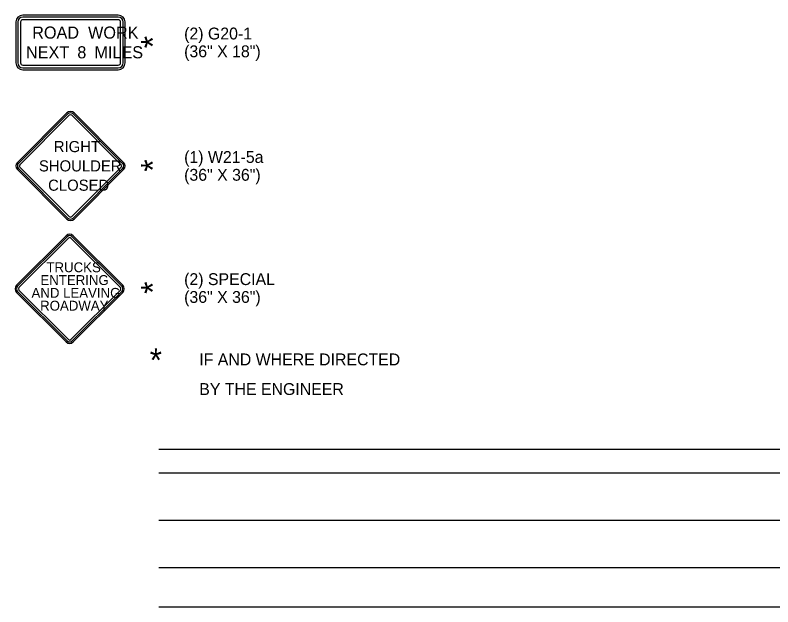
# Model space of a CAD drawing. Extents: x 913 to 1207, y 319 to 519.
# Drawn here: x 913.1 to 989.8, y 413.6 to 473.5 of the extents above; entities that cross this region are included whole.
import ezdxf

# ---------------------------------------------------------------- set-up
doc = ezdxf.new("R2010")
doc.units = 0
doc.layers.add('R_Annotation', color=7, linetype='Continuous')
doc.layers.add('R_Draft', color=7, linetype='Continuous')

msp = doc.modelspace()

# ---------------------------------------------------------------- linework, layer by layer
at = {"layer": 'R_Annotation'}
for p, q in [((923.547, 473.475), (913.89, 473.475)), ((923.547, 473.283), (913.89, 473.283)), ((923.547, 473.015), (913.89, 473.015)), ((913.201, 472.785), (913.201, 468.647)), ((913.392, 472.785), (913.392, 468.647)), ((913.66, 472.785), (913.66, 468.647)), ((923.777, 468.647), (923.777, 472.785)), ((924.045, 468.647), (924.045, 472.785)), ((924.236, 468.647), (924.236, 472.785)), ((913.89, 468.417), (923.547, 468.417)), ((913.89, 468.149), (923.547, 468.149)), ((913.89, 467.957), (923.547, 467.957)), ((913.349, 458.585), (918.361, 463.596)), ((913.448, 458.485), (918.46, 463.497)), ((913.588, 458.346), (918.599, 463.358)), ((918.838, 463.358), (923.849, 458.346)), ((918.977, 463.497), (923.989, 458.485)), ((919.076, 463.596), (924.088, 458.585)), ((918.361, 452.857), (913.349, 457.869)), ((918.46, 452.957), (913.448, 457.968)), ((918.599, 453.096), (913.588, 458.108)), ((923.849, 458.108), (918.838, 453.096)), ((923.989, 457.968), (918.977, 452.957)), ((924.088, 457.869), (919.076, 452.857)), ((913.268, 446.155), (918.28, 451.166)), ((913.368, 446.055), (918.379, 451.067)), ((913.507, 445.916), (918.519, 450.928)), ((918.757, 450.928), (923.769, 445.916)), ((918.896, 451.067), (923.908, 446.055)), ((918.996, 451.166), (924.007, 446.155)), ((918.28, 440.427), (913.268, 445.439)), ((918.379, 440.527), (913.368, 445.538)), ((918.519, 440.666), (913.507, 445.677)), ((923.769, 445.677), (918.757, 440.666)), ((923.908, 445.538), (918.896, 440.527)), ((924.007, 445.439), (918.996, 440.427))]:
    msp.add_line(p, q, dxfattribs=at)
for centre, radius, start, end in [((913.89, 472.785), 0.69, 90, 180), ((913.89, 472.785), 0.498, 90, 180), ((913.89, 472.785), 0.23, 90, 180), ((923.547, 472.785), 0.69, 360, 90), ((923.547, 472.785), 0.498, 360, 90), ((923.547, 472.785), 0.23, 360, 90), ((913.89, 468.647), 0.69, 180, 270), ((913.89, 468.647), 0.498, 180, 270), ((913.89, 468.647), 0.23, 180, 270), ((923.547, 468.647), 0.69, 270, 360), ((923.547, 468.647), 0.498, 270, 0), ((923.547, 468.647), 0.23, 270, 0), ((918.719, 463.238), 0.506, 45, 135), ((918.719, 463.238), 0.366, 45, 135), ((918.719, 463.238), 0.169, 45, 135), ((913.707, 458.227), 0.506, 135, 225), ((913.707, 458.227), 0.366, 135, 225), ((913.707, 458.227), 0.169, 135, 225), ((923.73, 458.227), 0.169, 315, 45), ((923.73, 458.227), 0.366, 315, 45), ((923.73, 458.227), 0.506, 315, 45), ((918.719, 453.215), 0.366, 225, 315), ((918.719, 453.215), 0.169, 225, 315), ((918.719, 453.215), 0.506, 225, 315), ((918.638, 450.808), 0.506, 45, 135), ((918.638, 450.808), 0.366, 45, 135), ((918.638, 450.808), 0.169, 45, 135), ((913.626, 445.797), 0.506, 135, 225), ((913.626, 445.797), 0.366, 135, 225), ((923.649, 445.797), 0.366, 315, 45), ((923.649, 445.797), 0.506, 315, 45), ((913.626, 445.797), 0.169, 135, 225), ((923.649, 445.797), 0.169, 315, 45), ((918.638, 440.785), 0.169, 225, 315), ((918.638, 440.785), 0.506, 225, 315), ((918.638, 440.785), 0.366, 225, 315)]:
    msp.add_arc(centre, radius, start, end, dxfattribs=at)
at = {"layer": 'R_Draft'}
for p, q in [((927.658, 429.592), (1014.46, 429.592)), ((927.658, 427.199), (1014.46, 427.199)), ((927.658, 422.411), (1014.46, 422.411)), ((927.658, 417.623), (1014.46, 417.623)), ((927.658, 413.633), (1014.46, 413.633))]:
    msp.add_line(p, q, dxfattribs=at)

# ---------------------------------------------------------------- texts
at = {"layer": 'R_Annotation'}
for s, height, rotation, p in [('ROAD  WORK', 1.2262, 360, (914.844, 471.099)), ('(2) G20-1', 1.2, 360, (930.211, 471.016)), ('*', 2.4, 90, (928.248, 470.13)), ('NEXT\u20028\u2002MILES', 1.22619, 360, (914.214, 469.107)), ('(36" X 18")', 1.2, 360, (930.211, 469.216)), ('RIGHT', 1.125, 360, (917.027, 459.622)), ('(1) W21-5a', 1.2, 360, (930.211, 458.527)), ('SHOULDER', 1.125, 360, (915.525, 457.669)), ('*', 2.4, 90, (928.248, 457.641)), ('(36" X 36")', 1.2, 360, (930.211, 456.727)), ('CLOSED', 1.125, 360, (916.452, 455.715)), ('TRUCKS', 1, 360, (916.284, 447.476)), ('ENTERING', 1, 360, (915.678, 446.181)), ('(2) SPECIAL', 1.2, 360, (930.211, 446.175)), ('*', 2.4, 90, (928.248, 445.289)), ('AND LEAVING', 1, 360, (914.775, 444.887)), ('(36" X 36")', 1.2, 360, (930.211, 444.375)), ('ROADWAY', 1, 360, (915.646, 443.593)), ('*', 2.4, 360, (926.724, 437.391))]:
    msp.add_text(s, height=height, rotation=rotation, dxfattribs=at).set_placement(p)
for s, p in [('IF AND WHERE DIRECTED ', (931.74, 438.059)), ('BY THE ENGINEER', (931.74, 435.059))]:
    msp.add_text(s, height=1.2, dxfattribs=at).set_placement(p)

doc.saveas('drawing.dxf')
